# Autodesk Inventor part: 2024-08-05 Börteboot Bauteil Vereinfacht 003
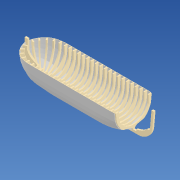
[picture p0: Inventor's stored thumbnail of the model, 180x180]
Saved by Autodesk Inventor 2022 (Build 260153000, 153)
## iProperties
Created: 2024-08
Part Number: 2024-08-05 Börteboot Bauteil Vereinfacht 003
Material: Generisch
Document SubType Name: Modellieren
Designer: i3meg
Density: 1 g/cm^3
Appearance: Vorgabe
Sheet Metal Rule: Standard_mm
Author: i3meg
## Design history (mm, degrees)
derived "2024-08-05 Börteboot 001.iam"
sketch "Skizze23"
  geometry: L1 (0, 40)-(16, 40) reference; L2 (16, 40)-(12, -2) reference; L3 (12, -2)-(7, -22) reference; L4 (7, -22)-(-2, -42) reference; L5 (-2, -42)-(-16, -60) reference; L6 (16, 40)-(18, 40); L7 (18, 40)-(14.861, -2.903); L8 (14.861, -2.903)-(13.907, -2.602); L9 (13.907, -2.602)-(9.669, -23.371); L10 (9.669, -23.371)-(8.806, -22.859); L11 (8.806, -22.859)-(0.442, -43.742); L12 (0.442, -43.742)-(-0.327, -43.096); L13 (-0.327, -43.096)-(-14.483, -62.588); L14 (-14.483, -62.588)-(-44.837, -65.349); L15 (-44.837, -65.349)-(-64.506, -66.341); L16 (-64.506, -66.341)-(-71.5, -79.942); L17 (-73.5, -76.942)-(-73.5, -79.942); L18 (-73.5, -79.942)-(-71.5, -79.942)
  constraints: 20 end point, 1 horizontal, 1 perpendicular, 1 vertical, 4 other
  dimensions: "d1821" = 2 distance of L1.end L6.end; "d1822" = 2 distance of L2.end L8.end; "d1823" = 3 distance of L2.end L7.end; "d1824" = 2 distance of L3.end L10.end; "d1825" = 3 distance of L3.end L9.end; "d1826" = 2 distance of L4.end L12.end; "d1827" = 3 distance of L4.end L11.end; "d1828" = 3 distance of L5.end L13.end; "d1829" = 3 distance of L17.start L17.end
sketch "Skizze24"
  geometry: L1 (16, 40)-(12, -4) reference; L2 (12, -4)-(8, -24) reference; L3 (8, -24)-(-1, -44) reference; L4 (-1, -44)-(-16, -62) reference; L5 (0, 40)-(16, 40) reference; L6 (16, 40)-(18, 40); L7 (18, 40)-(14.988, -4.272); L8 (14.988, -4.272)-(13.992, -4.181); L9 (13.992, -4.181)-(10.859, -24.909); L10 (10.859, -24.909)-(9.869, -24.713); L11 (9.869, -24.713)-(1.656, -45.395); L12 (1.656, -45.395)-(0.771, -44.93); L13 (0.771, -44.93)-(-14.749, -64.727); L14 (-73.5, -77.786)-(-73.5, -80.786); L15 (-73.5, -80.786)-(-71.5, -80.786); A1 r 219.794 centre (12.899, -279.885) between (-16, -62) and (-73.5, -77.786) reference; A2 r 202.647 centre (11.464, -265.671) between (-14.749, -64.727) and (-71.5, -80.786); 1 further point
  constraints: 20 end point, 2 point on circle, 1 centre point, 1 horizontal, 1 perpendicular, 1 vertical
  dimensions: "d161" = 2 distance of L1.start L6.end; "d166" = 2 distance of L1.end L8.end; "d167" = 3 distance of L1.end L7.end; "d169" = 2 distance of L2.end L10.end; "d170" = 3 distance of L2.end L9.end; "d173" = 2 distance of L3.end L12.end; "d174" = 3 distance of L3.end L11.end; "d175" = 3 distance of L4.end L13.end; "d1854" = 3 distance of L14.start L14.end
sketch "Skizze25"
  geometry: L1 (0, -46)-(-16, -64) reference; L2 (8, -26)-(0, -46) reference; L3 (12, -5)-(8, -26) reference; L4 (16, 40)-(12, -5) reference; L5 (16, 40)-(18, 40); L6 (18, 40)-(14.983, -5.319); L7 (14.983, -5.319)-(13.992, -5.177); L8 (13.992, -5.177)-(10.918, -26.695); L9 (10.918, -26.695)-(9.945, -26.465); L10 (9.945, -26.465)-(2.736, -47.231); L11 (2.736, -47.231)-(1.824, -46.821); L12 (1.824, -46.821)-(-14.767, -66.735); L13 (-73.5, -77.912)-(-73.5, -80.912); L14 (-73.5, -80.912)-(-71.5, -80.912); L15 (0, 40)-(16, 40) reference; A1 r 433.619 centre (-146.503, 349.514) between (-73.5, -77.915) and (-16, -64) reference; A2 r 310.184 centre (-118, 225.767) between (-71.5, -80.912) and (-14.767, -66.735); 1 further point
  constraints: 20 end point, 2 horizontal, 2 point on circle, 1 centre point, 1 perpendicular, 1 vertical
  dimensions: "d189" = 2 distance of L4.start L5.end; "d190" = 3 distance of L13.start L13.end; "d191" = 2 distance of L3.start L7.end; "d192" = 3 distance of L3.start L6.end; "d193" = 2 distance of L2.start L9.end; "d194" = 3 distance of L2.start L8.end; "d195" = 2 distance of L1.start L11.end; "d196" = 3 distance of L1.start L10.end; "d197" = 3 distance of L1.end L12.end; "d500" = 2 distance of L13.end L14.end
sketch "Skizze27"
  geometry: L1 (16, 40)-(12, -6) reference; L2 (12, -6)-(8, -27) reference; L3 (8, -27)-(0, -48) reference; L4 (0, -48)-(-16, -66) reference; L5 (16, 40)-(18, 40); L6 (18, 40)-(14.983, -6.315); L7 (14.983, -6.315)-(13.992, -6.173); L8 (13.992, -6.173)-(10.917, -27.702); L9 (10.917, -27.702)-(9.93, -27.524); L10 (9.93, -27.524)-(2.773, -49.144); L11 (2.773, -49.144)-(1.854, -48.75); L12 (1.854, -48.75)-(-13.819, -68.06); L13 (-73.5, -77.95)-(-73.5, -80.95); L14 (0, 40)-(16, 40) reference; A1 r 279.676 centre (-101.345, 200.336) between (-73.5, -77.95) and (-16, -66) reference; A2 r 259.061 centre (-97.972, 176.952) between (-73.5, -80.95) and (-13.819, -68.06); 1 further point
  constraints: 18 end point, 2 point on circle, 1 centre point, 1 horizontal, 1 perpendicular, 1 vertical
  dimensions: "d198" = 2 distance of L1.start L5.end; "d200" = 2 distance of L1.end L7.end; "d201" = 3 distance of L1.end L6.end; "d202" = 2 distance of L2.end L9.end; "d203" = 3 distance of L2.end L8.end; "d204" = 2 distance of L3.end L11.end; "d205" = 3 distance of L3.end L10.end; "d206" = 3 distance of L4.end L12.end; "d207" = 3 distance of L13.start L13.end
sketch "Skizze28"
  geometry: L1 (12, -6)-(16, 40) reference; L2 (8, -28)-(12, -6) reference; L3 (0, -49)-(8, -28) reference; L4 (-16, -67)-(0, -49) reference; L5 (-73.5, -77.992)-(-73.5, -80.992); L6 (16, 40)-(18, 40); L7 (18, 40)-(14.947, -6.561); L8 (14.947, -6.561)-(13.965, -6.374); L9 (13.965, -6.374)-(10.76, -29.176); L10 (10.76, -29.176)-(9.795, -28.883); L11 (9.795, -28.883)-(2.778, -50.133); L12 (2.778, -50.133)-(1.822, -49.824); L13 (1.822, -49.824)-(-13.372, -68.446); L14 (16, 40)-(0, 40) reference; A1 r 171.355 centre (-76.452, 93.337) between (-73.5, -77.992) and (-16, -67) reference; A2 r 176.524 centre (-78.941, 95.448) between (-73.5, -80.992) and (-13.372, -68.446); 1 further point
  constraints: 18 end point, 2 point on circle, 1 centre point, 1 horizontal, 1 vertical
  dimensions: "d224" = 3 distance of L5.start L5.end; "d225" = 2 distance of L1.end L6.end; "d226" = 2 distance of L1.start L8.end; "d227" = 3 distance of L1.start L7.end; "d228" = 2 distance of L2.start L10.end; "d229" = 3 distance of L2.start L9.end; "d230" = 2 distance of L3.start L12.end; "d231" = 3 distance of L3.start L11.end; "d232" = 3 distance of L4.start L13.end
sketch "Skizze37"
  geometry: L1 (12, -6)-(16, 40) reference; L2 (8, -28)-(12, -6) reference; L3 (0, -49)-(8, -28) reference; L4 (-16, -67)-(0, -49) reference; L5 (-73.5, -77.992)-(-73.5, -80.992); L6 (16, 40)-(0, 40) reference; L7 (16, 40)-(18, 40); L8 (18, 40)-(14.985, -6.302); L9 (14.985, -6.302)-(13.993, -6.17); L10 (13.993, -6.17)-(10.905, -28.749); L11 (10.905, -28.749)-(9.955, -28.421); L12 (9.955, -28.421)-(2.818, -50.028); L13 (2.818, -50.028)-(1.868, -49.714); L14 (1.868, -49.714)-(-13.461, -68.598); A1 r 171.355 centre (-76.452, 93.337) between (-73.5, -77.992) and (-16, -67) reference; A2 r 170.875 centre (-77.466, 89.837) between (-73.5, -80.992) and (-13.461, -68.598); 1 further point
  constraints: 18 end point, 2 point on circle, 1 centre point, 1 horizontal, 1 perpendicular, 1 vertical
  dimensions: "d286" = 3 distance of L5.start L5.end; "d287" = 2 distance of L1.end L7.end; "d288" = 2 distance of L1.start L9.end; "d289" = 3 distance of L1.start L8.end; "d290" = 2 distance of L2.start L11.end; "d291" = 3 distance of L2.start L10.end; "d292" = 2 distance of L3.start L13.end; "d293" = 3 distance of L3.start L12.end; "d294" = 3 distance of L4.start L14.end
sketch "Skizze38"
  geometry: L1 (9.955, -28.421)-(2.818, -50.028); L2 (2.818, -50.028)-(1.868, -49.714); L3 (1.868, -49.714)-(-13.461, -68.598); L4 (-73.5, -77.992)-(-73.5, -80.992); L5 (10.905, -28.749)-(9.955, -28.421); L6 (13.993, -6.17)-(10.905, -28.749); L7 (14.985, -6.302)-(13.993, -6.17); L8 (16, 40)-(18, 40); L9 (18, 40)-(14.985, -6.302); L10 (-16, -67)-(0, -49) reference; L11 (0, -49)-(8, -28) reference; L12 (8, -28)-(12, -6) reference; L13 (12, -6)-(16, 40) reference; L14 (16, 40)-(0, 40) reference; A1 r 170.875 centre (-77.466, 89.837) between (-73.5, -80.992) and (-13.461, -68.598); A2 r 171.355 centre (-76.452, 93.337) between (-73.5, -77.992) and (-16, -67) reference; 1 further point
  constraints: 18 end point, 2 point on circle, 1 centre point, 1 horizontal, 1 perpendicular, 1 vertical
  dimensions: "d295" = 3 distance of L4.start L4.end; "d296" = 2 distance of L8.start L8.end; "d533" = 2 distance of L12.end L6.start; "d534" = 3 distance of L12.end L7.start; "d535" = 2 distance of L11.end L1.start; "d536" = 3 distance of L11.end L5.start; "d537" = 2 distance of L10.end L2.end; "d538" = 3 distance of L10.end L1.end; "d539" = 3 distance of L10.start L3.end
sketch "Skizze39"
  geometry: L1 (9.955, -28.421)-(2.818, -50.028); L2 (2.818, -50.028)-(1.868, -49.714); L3 (1.868, -49.714)-(-13.461, -68.598); L4 (-73.5, -77.992)-(-73.5, -80.992); L5 (10.905, -28.749)-(9.955, -28.421); L6 (13.993, -6.17)-(10.905, -28.749); L7 (14.985, -6.302)-(13.993, -6.17); L8 (16, 40)-(18, 40); L9 (18, 40)-(14.985, -6.302); L10 (16, 40)-(0, 40) reference; L11 (12, -6)-(16, 40) reference; L12 (8, -28)-(12, -6) reference; L13 (0, -49)-(8, -28) reference; L14 (-16, -67)-(0, -49) reference; A1 r 170.875 centre (-77.466, 89.837) between (-73.5, -80.992) and (-13.461, -68.598); A2 r 171.355 centre (-76.452, 93.337) between (-73.5, -77.992) and (-16, -67) reference; 1 further point
  constraints: 18 end point, 2 point on circle, 1 centre point, 1 horizontal, 1 perpendicular, 1 vertical
  dimensions: "d304" = 3 distance of L4.start L4.end; "d305" = 2 distance of L8.start L8.end; "d540" = 2 distance of L11.start L6.start; "d541" = 3 distance of L11.start L7.start; "d542" = 2 distance of L12.start L1.start; "d543" = 3 distance of L12.start L5.start; "d544" = 2 distance of L13.start L2.end; "d545" = 3 distance of L13.start L1.end; "d546" = 3 distance of L14.start L3.end
sketch "Skizze40"
  geometry: L1 (9.955, -28.421)-(2.818, -50.028); L2 (2.818, -50.028)-(1.868, -49.714); L3 (1.868, -49.714)-(-13.461, -68.598); L4 (-73.5, -77.992)-(-73.5, -80.992); L5 (10.905, -28.749)-(9.955, -28.421); L6 (13.993, -6.17)-(10.905, -28.749); L7 (14.985, -6.302)-(13.993, -6.17); L8 (16, 40)-(18, 40); L9 (18, 40)-(14.985, -6.302); L10 (-16, -67)-(0, -49) reference; L11 (0, -49)-(8, -28) reference; L12 (8, -28)-(12, -6) reference; L13 (12, -6)-(16, 40) reference; L14 (16, 40)-(0, 40) reference; A1 r 170.875 centre (-77.466, 89.837) between (-73.5, -80.992) and (-13.461, -68.598); A2 r 171.355 centre (-76.452, 93.337) between (-73.5, -77.992) and (-16, -67) reference; 1 further point
  constraints: 18 end point, 2 point on circle, 1 centre point, 1 horizontal, 1 perpendicular, 1 vertical
  dimensions: "d313" = 3 distance of L4.start L4.end; "d314" = 2 distance of L8.start L8.end; "d547" = 2 distance of L12.end L6.start; "d548" = 3 distance of L12.end L7.start; "d549" = 2 distance of L11.end L1.start; "d550" = 3 distance of L11.end L5.start; "d551" = 2 distance of L10.end L2.end; "d552" = 3 distance of L10.end L1.end; "d553" = 3 distance of L10.start L3.end
sketch "Skizze41"
  geometry: L1 (9.955, -28.421)-(2.818, -50.028); L2 (2.818, -50.028)-(1.868, -49.714); L3 (1.868, -49.714)-(-13.461, -68.598); L4 (-73.5, -77.992)-(-73.5, -80.992); L5 (10.905, -28.749)-(9.955, -28.421); L6 (13.993, -6.17)-(10.905, -28.749); L7 (14.985, -6.302)-(13.993, -6.17); L8 (16, 40)-(18, 40); L9 (18, 40)-(14.985, -6.302); L10 (-16, -67)-(0, -49) reference; L11 (0, -49)-(8, -28) reference; L12 (8, -28)-(12, -6) reference; L13 (12, -6)-(16, 40) reference; L14 (16, 40)-(0, 40) reference; A1 r 170.875 centre (-77.466, 89.837) between (-73.5, -80.992) and (-13.461, -68.598); A2 r 171.355 centre (-76.452, 93.337) between (-73.5, -77.992) and (-16, -67) reference; 1 further point
  constraints: 18 end point, 2 point on circle, 1 centre point, 1 horizontal, 1 perpendicular, 1 vertical
  dimensions: "d322" = 3 distance of L4.start L4.end; "d323" = 2 distance of L8.start L8.end; "d554" = 2 distance of L12.end L6.start; "d555" = 3 distance of L12.end L7.start; "d556" = 2 distance of L11.end L1.start; "d557" = 3 distance of L11.end L5.start; "d558" = 2 distance of L10.end L2.end; "d559" = 3 distance of L10.end L1.end; "d560" = 3 distance of L10.start L3.end
sketch "Skizze42"
  geometry: L1 (9.955, -28.421)-(2.818, -50.028); L2 (2.818, -50.028)-(1.868, -49.714); L3 (1.868, -49.714)-(-13.461, -68.598); L4 (-73.5, -77.992)-(-73.5, -80.992); L5 (10.905, -28.749)-(9.955, -28.421); L6 (13.993, -6.17)-(10.905, -28.749); L7 (14.985, -6.302)-(13.993, -6.17); L8 (16, 40)-(18, 40); L9 (18, 40)-(14.985, -6.302); L10 (16, 40)-(0, 40) reference; L11 (12, -6)-(16, 40) reference; L12 (8, -28)-(12, -6) reference; L13 (0, -49)-(8, -28) reference; L14 (-16, -67)-(0, -49) reference; A1 r 170.875 centre (-77.466, 89.837) between (-73.5, -80.992) and (-13.461, -68.598); A2 r 171.355 centre (-76.452, 93.337) between (-73.5, -77.992) and (-16, -67) reference; 1 further point
  constraints: 18 end point, 2 point on circle, 1 centre point, 1 horizontal, 1 perpendicular, 1 vertical
  dimensions: "d331" = 3 distance of L4.start L4.end; "d332" = 2 distance of L8.start L8.end; "d561" = 2 distance of L11.start L6.start; "d562" = 3 distance of L11.start L7.start; "d563" = 2 distance of L12.start L1.start; "d564" = 3 distance of L12.start L5.start; "d566" = 2 distance of L13.start L2.end; "d567" = 3 distance of L13.start L1.end; "d568" = 3 distance of L14.start L3.end
sketch "Skizze43"
  geometry: L1 (9.955, -28.421)-(2.818, -50.028); L2 (2.818, -50.028)-(1.868, -49.714); L3 (1.868, -49.714)-(-13.461, -68.598); L4 (-73.5, -77.992)-(-73.5, -80.992); L5 (10.905, -28.749)-(9.955, -28.421); L6 (13.993, -6.17)-(10.905, -28.749); L7 (14.985, -6.302)-(13.993, -6.17); L8 (16, 40)-(18, 40); L9 (18, 40)-(14.985, -6.302); L10 (-16, -67)-(0, -49) reference; L11 (0, -49)-(8, -28) reference; L12 (8, -28)-(12, -6) reference; L13 (12, -6)-(16, 40) reference; L14 (16, 40)-(0, 40) reference; A1 r 170.875 centre (-77.466, 89.837) between (-73.5, -80.992) and (-13.461, -68.598); A2 r 171.355 centre (-76.452, 93.337) between (-73.5, -77.992) and (-16, -67) reference; 1 further point
  constraints: 18 end point, 2 point on circle, 1 centre point, 1 horizontal, 1 perpendicular, 1 vertical
  dimensions: "d340" = 3 distance of L4.start L4.end; "d341" = 2 distance of L8.start L8.end; "d569" = 2 distance of L12.end L6.start; "d570" = 3 distance of L12.end L7.start; "d571" = 2 distance of L11.end L1.start; "d572" = 3 distance of L11.end L5.start; "d573" = 2 distance of L10.end L2.end; "d574" = 3 distance of L10.end L1.end; "d575" = 3 distance of L10.start L3.end
sketch "Skizze44"
  geometry: L1 (9.955, -28.421)-(2.818, -50.028); L2 (2.818, -50.028)-(1.868, -49.714); L3 (1.868, -49.714)-(-13.461, -68.598); L4 (-73.5, -77.992)-(-73.5, -80.992); L5 (10.905, -28.749)-(9.955, -28.421); L6 (13.993, -6.17)-(10.905, -28.749); L7 (14.985, -6.302)-(13.993, -6.17); L8 (16, 40)-(18, 40); L9 (18, 40)-(14.985, -6.302); L10 (-16, -67)-(0, -49) reference; L11 (0, -49)-(8, -28) reference; L12 (8, -28)-(12, -6) reference; L13 (12, -6)-(16, 40) reference; L14 (16, 40)-(0, 40) reference; A1 r 170.875 centre (-77.466, 89.837) between (-73.5, -80.992) and (-13.461, -68.598); A2 r 171.355 centre (-76.452, 93.337) between (-73.5, -77.992) and (-16, -67) reference; 1 further point
  constraints: 18 end point, 2 point on circle, 1 centre point, 1 horizontal, 1 perpendicular, 1 vertical
  dimensions: "d349" = 3 distance of L4.start L4.end; "d350" = 2 distance of L8.start L8.end; "d576" = 2 distance of L12.end L6.start; "d577" = 3 distance of L12.end L7.start; "d578" = 2 distance of L11.end L1.start; "d579" = 3 distance of L11.end L5.start; "d580" = 2 distance of L10.end L2.end; "d581" = 3 distance of L10.end L1.end; "d582" = 3 distance of L10.start L3.end
sketch "Skizze45"
  geometry: L1 (9.955, -28.421)-(2.818, -50.028); L2 (2.818, -50.028)-(1.868, -49.714); L3 (1.868, -49.714)-(-13.461, -68.598); L4 (-73.5, -77.992)-(-73.5, -80.992); L5 (10.905, -28.749)-(9.955, -28.421); L6 (13.993, -6.17)-(10.905, -28.749); L7 (14.985, -6.302)-(13.993, -6.17); L8 (16, 40)-(18, 40); L9 (18, 40)-(14.985, -6.302); L10 (-16, -67)-(0, -49) reference; L11 (0, -49)-(8, -28) reference; L12 (8, -28)-(12, -6) reference; L13 (12, -6)-(16, 40) reference; L14 (16, 40)-(0, 40) reference; A1 r 170.875 centre (-77.466, 89.837) between (-73.5, -80.992) and (-13.461, -68.598); A2 r 171.355 centre (-76.452, 93.337) between (-73.5, -77.992) and (-16, -67) reference; 1 further point
  constraints: 18 end point, 2 point on circle, 1 centre point, 1 horizontal, 1 perpendicular, 1 vertical
  dimensions: "d358" = 3 distance of L4.start L4.end; "d359" = 2 distance of L8.start L8.end; "d583" = 2 distance of L12.end L6.start; "d584" = 3 distance of L12.end L7.start; "d585" = 2 distance of L11.end L1.start; "d586" = 3 distance of L11.end L5.start; "d587" = 2 distance of L10.end L2.end; "d588" = 3 distance of L10.end L1.end; "d589" = 3 distance of L10.start L3.end
sketch "Skizze46"
  geometry: L1 (9.955, -28.421)-(2.818, -50.028); L2 (2.818, -50.028)-(1.868, -49.714); L3 (1.868, -49.714)-(-13.461, -68.598); L4 (-73.5, -77.992)-(-73.5, -80.992); L5 (10.905, -28.749)-(9.955, -28.421); L6 (13.993, -6.17)-(10.905, -28.749); L7 (14.985, -6.302)-(13.993, -6.17); L8 (16, 40)-(18, 40); L9 (18, 40)-(14.985, -6.302); L10 (-16, -67)-(0, -49) reference; L11 (0, -49)-(8, -28) reference; L12 (8, -28)-(12, -6) reference; L13 (12, -6)-(16, 40) reference; L14 (16, 40)-(0, 40) reference; A1 r 170.875 centre (-77.466, 89.837) between (-73.5, -80.992) and (-13.461, -68.598); A2 r 171.355 centre (-76.452, 93.337) between (-73.5, -77.992) and (-16, -67) reference; 1 further point
  constraints: 18 end point, 2 point on circle, 1 centre point, 1 horizontal, 1 perpendicular, 1 vertical
  dimensions: "d367" = 3 distance of L4.start L4.end; "d368" = 2 distance of L8.start L8.end; "d590" = 2 distance of L12.end L6.start; "d591" = 3 distance of L12.end L7.start; "d592" = 2 distance of L11.end L1.start; "d593" = 3 distance of L11.end L5.start; "d594" = 2 distance of L10.end L2.end; "d595" = 3 distance of L10.end L1.end; "d596" = 3 distance of L10.start L3.end
sketch "Skizze47"
  geometry: L1 (9.407, -27.602)-(2.829, -48.999); L2 (2.829, -48.999)-(1.872, -48.705); L3 (1.872, -48.705)-(-13.883, -68.599); L4 (-73.5, -77.958)-(-73.5, -80.958); L5 (10.391, -27.803)-(9.407, -27.602); L6 (13.992, -6.173)-(10.391, -27.803); L7 (14.989, -6.26)-(13.992, -6.173); L8 (18, 40)-(14.989, -6.26); L9 (16, 40)-(0, 40); L10 (18, 40)-(16, 40); L11 (-16.421, -67)-(0, -48) reference; L12 (0, -48)-(7.5, -27) reference; L13 (7.5, -27)-(12, -6) reference; L14 (12, -6)-(16, 40) reference; A1 r 170.875 centre (-77.82, 89.863) between (-73.5, -80.958) and (-13.883, -68.599); A2 r 279.676 centre (-97.402, 200.695) between (-73.5, -77.958) and (-16.421, -67) reference; 1 further point
  constraints: 18 end point, 2 point on circle, 1 centre point, 1 horizontal, 1 perpendicular, 1 vertical
  dimensions: "d376" = 3 distance of L4.start L4.end; "d377" = 2 distance of L14.end L8.start; "d947" = 2 distance of L13.end L6.start; "d948" = 3 distance of L13.end L7.start; "d949" = 2 distance of L12.end L1.start; "d950" = 3 distance of L12.end L5.start; "d951" = 2 distance of L11.end L2.end; "d952" = 3 distance of L11.end L1.end; "d953" = 3 distance of L11.start L3.end
sketch "Skizze48"
  geometry: L1 (12, -5)-(16, 40) reference; L2 (7, -26)-(12, -5) reference; L3 (-1, -46)-(7, -26) reference; L4 (-17, -65)-(-1, -46) reference; L5 (-73.5, -77.921)-(-73.5, -80.921); L6 (0, 40)-(16, 40) reference; L7 (16, 40)-(18, 40); L8 (18, 40)-(14.976, -5.383); L9 (14.976, -5.383)-(13.983, -5.258); L10 (13.983, -5.258)-(9.918, -26.697); L11 (9.918, -26.697)-(8.961, -26.393); L12 (8.961, -26.393)-(1.755, -47.189); L13 (1.755, -47.189)-(0.806, -46.86); L14 (0.806, -46.86)-(-15.718, -67.712); L15 (-73.5, -80.921)-(-71.5, -80.921); A1 r 433.619 centre (-141.7, 350.301) between (-73.5, -77.921) and (-17, -65) reference; A2 r 288.501 centre (-109.755, 205.033) between (-71.5, -80.921) and (-15.718, -67.712); 1 further point
  constraints: 20 end point, 2 horizontal, 2 point on circle, 1 centre point, 1 perpendicular, 1 vertical
  dimensions: "d425" = 3 distance of L5.start L5.end; "d426" = 2 distance of L1.end L7.end; "d427" = 2 distance of L1.start L9.end; "d428" = 3 distance of L1.start L8.end; "d429" = 2 distance of L2.start L11.end; "d430" = 3 distance of L2.start L10.end; "d431" = 2 distance of L3.start L13.end; "d432" = 3 distance of L3.start L12.end; "d433" = 3 distance of L4.start L14.end; "d501" = 2 distance of L5.end L15.end
sketch "Skizze49"
  geometry: L1 (12, -4)-(16, 40) reference; L2 (6.5, -24)-(12, -4) reference; L3 (-3, -44)-(6.5, -24) reference; L4 (-18, -62)-(-3, -44) reference; L5 (-73.5, -77.772)-(-73.5, -80.772); L6 (16, 40)-(18, 40); L7 (18, 40)-(14.988, -4.272); L8 (14.988, -4.272)-(13.992, -4.181); L9 (13.992, -4.181)-(9.365, -24.889); L10 (9.365, -24.889)-(8.428, -24.532); L11 (8.428, -24.532)-(-0.257, -45.215); L12 (-0.257, -45.215)-(-1.132, -44.714); L13 (-1.132, -44.714)-(-16.717, -64.712); L14 (-73.5, -80.772)-(-71.5, -80.772); L15 (16, 40)-(0, 40) reference; A1 r 219.794 centre (14.094, -279.438) between (-18, -62) and (-73.5, -77.853) reference; A2 r 235.378 centre (21.621, -296.947) between (-16.717, -64.712) and (-71.5, -80.772); 1 further point
  constraints: 20 end point, 2 horizontal, 2 point on circle, 1 centre point, 1 vertical
  dimensions: "d434" = 3 distance of L5.start L5.end; "d435" = 2 distance of L1.end L6.end; "d436" = 2 distance of L1.start L8.end; "d437" = 3 distance of L1.start L7.end; "d438" = 2 distance of L2.start L10.end; "d439" = 3 distance of L2.start L9.end; "d440" = 3 distance of L13.end L4.start; "d450" = 2 distance of L3.start L12.end; "d451" = 3 distance of L3.start L11.end; "d502" = 2 distance of L5.end L14.end
sketch "Skizze51"
  geometry: L1 (12, -3)-(16, 40) reference; L2 (5, -22)-(12, -3) reference; L3 (-5, -41)-(5, -22) reference; L4 (-20, -57)-(-5, -41) reference; L5 (-73.5, -76.936)-(-73.5, -79.936); L6 (16, 40)-(18, 40); L7 (18, 40)-(14.987, -3.278); L8 (14.987, -3.278)-(13.991, -3.185); L9 (13.991, -3.185)-(7.751, -23.196); L10 (7.751, -23.196)-(6.845, -22.771); L11 (6.845, -22.771)-(-2.328, -42.363); L12 (-2.328, -42.363)-(-3.246, -41.961); L13 (-3.246, -41.961)-(-18.862, -59.776); L14 (-73.5, -79.936)-(-71.5, -79.936); L15 (16, 40)-(0, 40) reference; A1 r 155.061 centre (9.356, -212.248) between (-18.862, -59.776) and (-71.5, -79.936); 1 further point
  constraints: 20 end point, 2 horizontal, 2 point on circle, 1 centre point, 1 perpendicular, 1 vertical, 1 other
  dimensions: "d452" = 3 distance of L5.start L5.end; "d453" = 2 distance of L1.end L6.end; "d454" = 3 distance of L4.start L13.end; "d455" = 2 distance of L1.start L8.end; "d456" = 3 distance of L1.start L7.end; "d457" = 2 distance of L2.start L10.end; "d458" = 3 distance of L2.start L9.end; "d459" = 2 distance of L3.start L12.end; "d460" = 3 distance of L3.start L11.end; "d503" = 2 distance of L5.end L14.end
sketch "Skizze64"
  geometry: L1 (16, 40)-(0, 40) reference; L2 (12, -1)-(16, 40) reference; L3 (4, -20)-(12, -1) reference; L4 (-7, -38)-(4, -20) reference; L5 (-23, -53)-(-7, -38) reference; L6 (-72.5, -75.584)-(-72.5, -78.584); L7 (-72.5, -78.584)-(-70.5, -78.584); L8 (16, 40)-(18, 40); L9 (18, 40)-(14.986, -1.291); L10 (14.986, -1.291)-(13.991, -1.194); L11 (13.991, -1.194)-(6.839, -20.969); L12 (6.839, -20.969)-(5.92, -20.56); L13 (5.92, -20.56)-(-4.44, -39.564); L14 (-4.44, -39.564)-(-5.293, -39.043); L15 (-5.293, -39.043)-(-21.189, -55.392); A1 r 119.222 centre (3.554, -172.018) between (-21.189, -55.392) and (-70.5, -78.584); 2 further points
  constraints: 20 end point, 2 point on circle, 1 centre point, 1 horizontal, 1 perpendicular, 1 vertical, 1 other
  dimensions: "d1154" = 3 distance of L6.start L6.end; "d1155" = 2 distance of L6.end L7.end; "d1156" = 2 distance of L1.start L8.end; "d1157" = 2 distance of L2.start L10.end; "d1158" = 3 distance of L2.start L9.end; "d1159" = 2 distance of L3.start L12.end; "d1160" = 3 distance of L3.start L11.end; "d1162" = 2 distance of L4.start L14.end; "d1163" = 3 distance of L4.start L13.end; "d1164" = 3 distance of L5.start L15.end
workplane "Arbeitsebene10"
sketch "Skizze66"
  geometry: L1 (-149, 78)-(-149, 73.5) reference; L2 (-133, 73.5)-(-149, 73.5) reference; L3 (-133, 78)-(-133, 73.5) reference; L4 (-149, 78)-(545.913, 78); L5 (509.887, 78)-(509.887, 73.5) reference; L6 (521.933, 73.5)-(509.887, 73.5) reference; L7 (521.933, 78)-(521.933, 73.5) reference; L8 (-149, 82.5)-(-149, 73.5) reference; L9 (419.933, 78)-(532.121, 78); L10 (419.933, 78)-(528.824, 78); L11 (419.933, 78)-(532.968, 78); L12 (419.933, 78)-(537.839, 78); L13 (-47, 78)-(63.58, 78); L14 (-47, 78)-(63.869, 78); L15 (-47, 78)-(64.441, 78); L16 (-47, 78)-(66.003, 78); L17 (521.933, 78)-(509.887, 78) reference; L18 (-133, 78)-(-149, 78) reference; L19 (-104, 73.5)-(441, 73.5) reference; L20 (-29, 63)-(-29, 0) reference; L21 (419.933, 73.5)-(444.387, -41.549); L22 (414, 1)-(414, -15) reference; L23 (-49.182, 75.75)-(66.519, 75.75); L24 (-35, 75.75)-(-53.663, -30.096); L25 (-29, 78)-(-29, 63) reference; L26 (-29, 0)-(-29, -16) reference; L27 (-45, 75.75)-(-82.627, -17.38); L28 (-55, 75.75)-(-113.479, -7.767); L29 (-68, 75.75)-(-134.552, 17.897); L30 (-87, 75.75)-(-153.724, 43.207); L31 (429.933, 75.75)-(466.475, -14.695); L32 (439.933, 75.75)-(488.874, 3.191); L33 (449.933, 75.75)-(506.944, 22.586); L34 (459.933, 75.75)-(517.489, 45.147); C1 r 92.5 at (-47, 78); C2 r 92.5 at (419.933, 78); A1 r 1.607 centre (418.36, 73.166) between (419.933, 73.5) and (419.933, 73.5); 1 further point
  constraints: 40 end point, 10 horizontal, 5 point on line, 3 centre point, 2 point on circle, 1 midpoint, 1 tangent
  dimensions: "d1205" = 185 diameter of C1; "d1206" = 102 distance from line of L8 L13.start; "d1207" = 185 diameter of C2; "d1208" = 102 distance from line of L7 L9.start; "d1459" = 12 deg angle of L22 L21; "d1521" = 6 distance from line of L25 L24.start; "d1522" = 10 deg angle of L26 L24; "d1523" = 10 distance of L24.start L27.start; "d1524" = 12 deg angle of L24 L27; "d1525" = 10 distance of L27.start L28.start; "d1526" = 13 deg angle of L27 L28; "d1527" = 13 distance of L28.start L29.start; "d1528" = 14 deg angle of L28 L29; "d1529" = 19 distance of L29.start L30.start; "d1530" = 15 deg angle of L29 L30; "d1531" = 10 horizontal distance of L21.start L31.start; "d1532" = 10 deg angle of L21 L31; "d1533" = 10 distance of L31.start L32.start; "d1534" = 12 deg angle of L32 L31; "d1535" = 10 distance of L32.start L33.start; "d1536" = 10 distance of L33.start L34.start; "d1537" = 13 deg angle of L33 L32; "d1538" = 15 deg angle of L33 L34
  node "Projizierte Kontur63"
  node "Projizierte Kontur64"
workplane "Arbeitsebene15"
sketch "Skizze80"
  geometry: L1 (95.58, -2.549)-(95.58, 13.005); L2 (0, 91.743)-(40, 86.743); L3 (35, 75.743)-(0, 75.743); L4 (40, 86.743)-(59, 80.743); L5 (59, 80.743)-(78, 72.743); L6 (78, 72.743)-(96, 59.743); L7 (95.58, -2.549)-(114.959, -2.549); L8 (114.5, 2.665)-(114.959, -2.549); L9 (0, 75.743)-(0, 91.743); L10 (-69.42, 202.197)-(-69.42, -260.249) reference; L11 (165.084, -24.257)-(-108.504, -24.257) reference; 2 further points; 1 other entity
  constraints: 18 end point, 1 vertical, 7 other
  dimensions: "d1542" = 100 distance between parallel lines of L3 L11; "d1543" = 16 distance of L3.end L2.start; "d1544" = 165 distance between parallel lines of L10 L1; "d1545" = 35 distance from line of L9 L3.start; "d1546" = 69.42029 distance between parallel lines of L10 L9; "d1547" = 40 distance from line of L2.end L9; "d1807" = 19 horizontal distance of L4.end L2.end; "d1808" = 19 horizontal distance of L5.end L4.end; "d1809" = 18 horizontal distance of L6.end L5.end; "d1846" = 97 distance from line of L11 L5.end; "d1847" = 84 distance from line of L11 L6.end; "d1852" = 105 distance from line of L11 L4.end; "d1853" = 111 distance from line of L11 L2.end
extrude "Extrusion19" join sketch "Skizze80" distance "d1540" = 6; taper "d1541" = 0 deg
workplane "Arbeitsebene16"
sketch "Skizze81"
  geometry: L1 (0, 75.114)-(33, 75.114); L2 (0, 91.114)-(0, 75.114); L3 (35, 85.614)-(0, 91.114); L4 (53, 79.614)-(35, 85.614); L5 (93.58, 14.427)-(93.58, -3.051); L6 (93.58, -3.051)-(111.213, -3.051); L7 (71, 70.614)-(53, 79.614); L8 (89, 59.614)-(71, 70.614); L9 (111.213, 4.975)-(111.213, -3.051); L10 (-69.42, 241.226)-(-69.42, -400.95) reference; L11 (165.084, -50.386)-(-108.504, -50.386) reference; 2 further points; 1 other entity
  constraints: 18 end point, 1 vertical, 7 other
  dimensions: "d1553" = 69.42029 distance between parallel lines of L10 L2; "d1554" = 125.5 distance between parallel lines of L11 L1; "d1555" = 16 distance of L1.start L2.start; "d1556" = 33 distance of L1.start L1.end; "d1557" = 35 distance from line of L3.start L2; "d1803" = 130 distance from line of L11 L4.start; "d1804" = 121 distance from line of L11 L7.start; "d1805" = 110 distance from line of L11 L8.start; "d1806" = 136 distance from line of L11 L3.start; "d2263" = 18 horizontal distance of L4.start L3.start; "d2264" = 18 horizontal distance of L7.start L4.start; "d2265" = 18 horizontal distance of L8.start L7.start
extrude "Extrusion20" join sketch "Skizze81" distance "d1549" = 6; taper "d1550" = 0 deg
workplane "Arbeitsebene17"
sketch "Skizze83"
  geometry: L1 (92.58, -4.895)-(112.58, -4.895); L2 (79.58, 57.469)-(63, 67.969); L3 (63, 67.969)-(46, 75.969); L4 (46, 75.969)-(29, 80.969); L5 (29, 80.969)-(0, 85.969); L6 (0, 85.969)-(0, 69.969); L7 (0, 69.969)-(22.505, 69.969); L8 (92.58, 9.184)-(92.58, -4.895); L9 (92.58, -4.895)-(112.58, -4.895); L10 (112.58, 0.34)-(112.58, -4.895); L11 (-69.42, 267.71)-(-69.42, -537.283) reference; L12 (165.084, -80.031)-(-108.504, -80.031) reference; 2 further points; 1 other entity
  constraints: 20 end point, 1 horizontal, 1 vertical, 10 other
  dimensions: "d1559" = 69.42029 distance between parallel lines of L11 L6; "d1563" = 162 distance between parallel lines of L11 L8; "d1564" = 20 distance between parallel lines of L10 L8; "d1565" = 149 distance from line of L11 L2.start; "d1566" = 29 distance from line of L6 L4.end; "d1579" = 150 distance between parallel lines of L12 L7; "d1580" = 16 distance of L5.end L6.end; "d1799" = 137.5 distance from line of L12 L2.start; "d1800" = 17 horizontal distance of L4.end L3.end; "d1801" = 17 horizontal distance of L3.end L2.end; "d1802" = 148 distance from line of L12 L2.end; "d2245" = 156 distance from line of L12 L3.end; "d2246" = 161 distance from line of L12 L4.end
extrude "Extrusion22" join sketch "Skizze83" distance "d1567" = 6; taper "d1568" = 0 deg
workplane "Arbeitsebene18"
sketch "Skizze84"
  geometry: L1 (0, 57.926)-(25, 57.926); L2 (24, 71.131)-(0, 73.926); L3 (40, 67.888)-(24, 71.131); L4 (56, 59.888)-(40, 67.888); L5 (70, 49.888)-(56, 59.888); L6 (90.58, 3.87)-(90.58, -10.846); L7 (90.58, -10.846)-(110.58, -10.846); L8 (110.58, -10.846)-(110.58, -5.765); L9 (0, 73.926)-(0, 57.926); L10 (-69.42, 275.079)-(-69.42, -658.915) reference; L11 (165.084, -113.112)-(-108.504, -113.112) reference; L12 (0, 0)-(0, 88.182) reference; 2 further points; 1 other entity
  constraints: 18 end point, 7 other
  dimensions: "d1571" = 69.42029 distance between parallel lines of L10 L9; "d1572" = 171.03848 distance between parallel lines of L11 L1; "d1573" = 16 distance of L2.end L1.start; "d1574" = 25 distance of L1.start L1.end; "d1575" = 24 horizontal distance of L2.start L2.end; "d1576" = 160 distance between parallel lines of L10 L6; "d1794" = 14 horizontal distance of L5.start L4.start; "d1795" = 16 horizontal distance of L4.start L3.start; "d1796" = 16 horizontal distance of L3.start L2.start; "d1797" = 163 distance from line of L11 L5.start; "d1798" = 173 distance from line of L11 L4.start; "d2063" = 181 distance from line of L11 L3.start
extrude "Extrusion23" join sketch "Skizze84" distance "d1577" = 6; taper "d1578" = 0 deg
workplane "Arbeitsebene19"
sketch "Skizze85"
  geometry: L1 (0, 37.845)-(17.195, 37.845); L2 (80.58, -14.142)-(80.58, -26); L3 (80.58, -26)-(110.58, -26); L4 (66, 24.845)-(51, 37.845); L5 (51, 37.845)-(37, 46.845); L6 (37, 46.845)-(22, 52.845); L7 (22, 52.845)-(0, 53.845); L8 (0, 53.845)-(0, 37.845); L9 (-69.42, 297.978)-(-69.42, -761.789) reference; L10 (259.95, -150.155)-(-124.315, -150.155) reference; L11 (110.58, -26)-(110.58, -21.093) reference; L12 (110.58, -26)-(110.58, -20.227); A1 r 167.263 centre (205.055, 117.799) between (66, 24.845) and (110.58, -20.227); A2 r 93.737 centre (-4.574, -53.329) between (80.58, -14.145) and (17.195, 37.845); 2 further points
  constraints: 18 end point, 4 point on circle, 2 centre point, 1 collinear, 1 point on line
  dimensions: "d1582" = 69.42029 distance between parallel lines of L9 L8; "d1583" = 188 distance between parallel lines of L10 L1; "d1584" = 150 distance between parallel lines of L9 L2; "d1585" = 16 distance of L7.end L1.start; "d1588" = 15 horizontal distance of L5.end L6.end; "d1589" = 14 horizontal distance of L5.end L4.end; "d1590" = 15 horizontal distance of L4.end L4.start; "d1591" = 175 distance from line of L10 L4.start; "d1592" = 188 distance from line of L10 L4.end; "d2068" = 203 distance from line of L10 L6.end; "d2247" = 22 horizontal distance of L7.end L6.end; "d2248" = 197 distance from line of L10 L5.end
extrude "Extrusion24" join sketch "Skizze85" distance "d1586" = 6; taper "d1587" = 0 deg
extrude "Extrusion25" cut sketch "Skizze86" extent not by distance; stored distance "d1593" = 0; taper "d1594" = 0 deg
sketch "Skizze88"
  geometry: L1 (91.743, 0)-(75.743, 0) reference; L2 (86.743, -40)-(91.743, 0) reference; L3 (80.743, -59)-(86.743, -40) reference; L4 (72.743, -78)-(80.743, -59) reference; L5 (59.743, -96)-(72.743, -78) reference; L6 (3.343, -113.359)-(3.343, -117.359); L7 (3.343, -117.359)-(5.343, -117.359); L8 (91.743, 0)-(93.743, 0); L9 (93.743, 0)-(89.731, -40.271); L10 (89.731, -40.271)-(88.73, -40.229); L11 (88.73, -40.229)-(83.574, -59.991); L12 (83.574, -59.991)-(82.596, -59.752); L13 (82.596, -59.752)-(74.952, -80.03); L14 (74.952, -80.03)-(74.214, -79.355); L15 (74.214, -79.355)-(61.106, -98.673); L16 (61.106, -98.673)-(25.92, -101.132); L17 (25.92, -101.132)-(8.876, -105.74); L18 (8.876, -105.74)-(5.343, -117.359); 1 further point
  constraints: 20 end point, 1 horizontal, 1 perpendicular, 1 vertical, 4 other
  dimensions: "d1605" = 4 distance of L6.start L6.end; "d1606" = 2 distance of L6.end L7.end; "d1607" = 2 distance of L1.start L8.end; "d1608" = 2 distance of L2.start L10.end; "d1609" = 3 distance of L2.start L9.end; "d1610" = 2 distance of L3.start L12.end; "d1611" = 3 distance of L3.start L11.end; "d1612" = 2 distance of L4.start L14.end; "d1613" = 3 distance of L4.start L13.end; "d1614" = 3 distance of L5.start L15.end
sketch "Skizze89"
  geometry: L1 (91.114, 0)-(75.114, 0) reference; L2 (85.614, -35)-(91.114, 0) reference; L3 (79.614, -53)-(85.614, -35) reference; L4 (70.614, -71)-(79.614, -53) reference; L5 (59.614, -89)-(70.614, -71) reference; L6 (4.975, -111.213)-(4.975, -114.213); L7 (4.975, -114.213)-(6.975, -114.213); L8 (91.114, 0)-(93.114, 0); L9 (93.114, 0)-(88.577, -35.469); L10 (88.577, -35.469)-(87.589, -35.312); L11 (87.589, -35.312)-(82.447, -53.985); L12 (82.447, -53.985)-(81.472, -53.739); L13 (81.472, -53.739)-(73.19, -72.537); L14 (73.19, -72.537)-(72.286, -72.096); L15 (72.286, -72.096)-(60.837, -91.739); L16 (60.837, -91.739)-(26.244, -97.38); L17 (26.244, -97.38)-(13.764, -101.005); L18 (13.764, -101.005)-(6.975, -114.213); 1 further point
  constraints: 20 end point, 1 horizontal, 1 perpendicular, 1 vertical, 4 other
  dimensions: "d1627" = 3 distance of L6.start L6.end; "d1628" = 2 distance of L6.end L7.end; "d1629" = 2 distance of L1.start L8.end; "d1630" = 2 distance of L2.start L10.end; "d1631" = 3 distance of L2.start L9.end; "d1632" = 2 distance of L3.start L12.end; "d1633" = 3 distance of L3.start L11.end; "d1634" = 2 distance of L4.start L14.end; "d1635" = 3 distance of L4.start L13.end; "d1636" = 3 distance of L5.start L15.end
sketch "Skizze90"
  geometry: L1 (85.969, 0)-(69.969, 0) reference; L2 (80.969, -29)-(85.969, 0) reference; L3 (75.969, -46)-(80.969, -29) reference; L4 (67.969, -63)-(75.969, -46) reference; L5 (57.469, -79.58)-(67.969, -63) reference; L6 (6.948, -102.881)-(6.948, -108.881); L7 (6.948, -108.881)-(8.948, -108.881); L8 (85.969, 0)-(87.969, 0); L9 (87.969, 0)-(84.093, -29.693); L10 (84.093, -29.693)-(83.117, -29.476); L11 (83.117, -29.476)-(79.037, -46.909); L12 (79.037, -46.909)-(77.886, -46.568); L13 (77.886, -46.568)-(70.605, -64.432); L14 (70.605, -64.432)-(69.726, -63.955); L15 (69.726, -63.955)-(59.113, -82.089); L16 (59.113, -82.089)-(38.286, -89.34); L17 (38.286, -89.34)-(13.441, -97.636); L18 (13.441, -97.636)-(8.948, -108.881); 1 further point
  constraints: 20 end point, 1 horizontal, 1 perpendicular, 1 vertical, 4 other
  dimensions: "d1651" = 6 distance of L6.start L6.end; "d1652" = 2 distance of L6.end L7.end; "d1653" = 2 distance of L1.start L8.end; "d1654" = 2.2 distance of L2.start L10.end; "d1655" = 3.2 distance of L2.start L9.end; "d1656" = 2 distance of L3.start L12.end; "d1657" = 3.2 distance of L3.start L11.end; "d1658" = 2 distance of L4.start L14.end; "d1659" = 3 distance of L4.start L13.end; "d1660" = 3 distance of L5.start L15.end
sketch "Skizze91"
  geometry: L1 (73.926, 0)-(57.926, 0) reference; L2 (71.131, -24)-(73.926, 0) reference; L3 (67.888, -40)-(71.131, -24) reference; L4 (59.888, -56)-(67.888, -40) reference; L5 (49.888, -70)-(59.888, -56) reference; L6 (10.332, -94.989)-(10.332, -99.989); L7 (10.332, -99.989)-(12.332, -99.989); L8 (73.926, 0)-(75.926, 0); L9 (75.926, 0)-(74.115, -24.309); L10 (74.115, -24.309)-(73.12, -24.206); L11 (73.12, -24.206)-(70.763, -40.855); L12 (70.763, -40.855)-(69.798, -40.593); L13 (69.798, -40.593)-(63.273, -58.131); L14 (63.273, -58.131)-(62.309, -57.772); L15 (62.309, -57.772)-(52.364, -73.141); A1 r 282.977 centre (189.391, -320.729) between (52.364, -73.141) and (12.332, -99.989); 1 further point
  constraints: 20 end point, 2 perpendicular, 2 point on circle, 1 centre point, 1 horizontal, 1 vertical, 1 other
  dimensions: "d1675" = 5 distance of L6.start L6.end; "d1676" = 2 distance of L6.end L7.end; "d1677" = 2 distance of L1.start L8.end; "d1678" = 2 distance of L2.start L10.end; "d1679" = 3 distance of L2.start L9.end; "d1680" = 2 distance of L3.start L12.end; "d1681" = 3 distance of L3.start L11.end; "d1682" = 3 distance of L4.start L14.end; "d1683" = 4 distance of L4.start L13.end; "d1684" = 4 distance of L5.start L15.end
feature "Verdickung11" dims "d1940" = 2, "d1941" = 2
feature "Verdickung12" dims "d1942" = 2, "d1943" = 2
feature "Verdickung13" dims "d1944" = 2, "d1945" = 2
feature "Verdickung14" dims "d1946" = 2, "d1947" = 2
feature "Verdickung15" dims "d1948" = 2, "d1949" = 2
feature "Verdickung16" dims "d1950" = 2, "d1951" = 2
feature "Verdickung17" dims "d1952" = 2, "d1953" = 2
sketch "Skizze94"
  geometry: L1 (-27.129, 91.87)-(-29, 126); L2 (-24.078, 74.319)-(-27.129, 91.87); L3 (-10.001, 59.923)-(-24.078, 74.319); L4 (8.284, 46.946)-(-10.001, 59.923); L5 (0, 75)-(-11, 77) reference; L6 (-19, 145)-(-35, 145) reference; L7 (-35, 145)-(-35, 79.993) reference; L8 (-29, 126)-(-31, 126); L9 (-30, 91)-(-29.043, 91.29); L10 (-29.043, 91.29)-(-27, 75); L11 (-27, 75)-(-25.903, 75.138); L12 (-25.903, 75.138)-(-13, 60); L13 (-13, 60)-(-11.986, 60.167); L14 (-11.986, 60.167)-(6, 45); L15 (14.029, 42.105)-(14.029, 40.105); L16 (-31, 126)-(-30.908, 106); L17 (-30.908, 106)-(-29.907, 106); L18 (-29.907, 106)-(-30, 91); A1 r 12 centre (-11, 89) between (-23, 89) and (-11, 77) reference; A2 r 24 centre (-11, 79.993) between (-35, 79.993) and (-23.36, 59.42) reference; A3 r 55.926 centre (-45.925, 10.152) between (10, 10) and (-21.487, 60.456) reference; A4 r 13.44 centre (3.46, 31.803) between (14.029, 40.105) and (6, 45); 4 further points; 2 other entities
  constraints: 30 end point, 2 horizontal, 2 point on circle, 1 centre point, 1 vertical, 5 other
  dimensions: "d2034" = 2 distance of L1.end L8.end; "d2035" = 2 distance of L1.start L9.end; "d2036" = 3 distance of L1.start L9.start; "d2037" = 2 distance of L2.start L11.end; "d2038" = 3 distance of L2.start L10.end; "d2039" = 2 distance of L3.start L13.end; "d2040" = 3 distance of L3.start L12.end; "d2041" = 3 distance of L4.start L14.end; "d2042" = 4 distance from line of L7 L8.end; "d2043" = 8 distance from line of L7 L10.end; "d2044" = 22 distance from line of L7 L12.end; "d2045" = 41 distance from line of L7 L14.end; "d2046" = 2 distance of L15.start L15.end; "d2058" = 19 distance between parallel lines of L6 L8; "d2060" = 16 vertical distance of L9.start L10.end; "d2061" = 15 vertical distance of L10.end L12.end; "d2062" = 15 vertical distance of L14.end L12.end; "d2064" = 5 distance from line of L7 L9.start; "d2065" = 2 distance from line of L1 L17.end; "d2066" = 3 distance from line of L1 L16.end; "d2067" = 20 distance between parallel lines of L8 L17; "d2142" = 15 vertical distance of L16.end L9.start
feature "Erhebung71" dims "d2191" = 0, "d2192" = 90 deg, "d2193" = 0, "d2194" = 90 deg, "d2195" = 0, "d2196" = 90 deg, "d2197" = 0, "d2198" = 90 deg, "d2199" = 0, "d2200" = 90 deg, "d2201" = 0, "d2202" = 90 deg, "d2203" = 0, "d2204" = 90 deg, "d2205" = 0, "d2206" = 90 deg, "d2207" = 0, "d2208" = 90 deg, "d2209" = 0, "d2210" = 90 deg, "d2211" = 0, "d2212" = 90 deg, "d2213" = 0, "d2214" = 90 deg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
feature "Erhebung73" dims "d2249" = 0, "d2250" = 90 deg, "d2251" = 0, "d2252" = 90 deg, "d2253" = 0, "d2254" = 90 deg, "d2255" = 0, "d2256" = 90 deg
feature "Erhebung74" dims "d2257" = 0, "d2258" = 90 deg, "d2259" = 0, "d2260" = 90 deg, "d2261" = 0, "d2262" = 90 deg
feature "Verdickung43" dims "d2268" = 9, "d2269" = 9
feature "Verdickung44" dims "d2270" = 8, "d2271" = 10
feature "Verdickung45" dims "d2272" = 4, "d2273" = 11
feature "Verdickung46" dims "d2274" = 2.5, "d2275" = 11
mirror "Spiegeln9"
workplane "Arbeitsebene23"
node "Volumenkörper1"
feature "Verdickung10" dims "d2266" = 9, "d2267" = 11
node "2024-08-05 Börteboot Kiel 001.ipt:1" dims "d0" = 10
node "2024-08-05 Börteboot Spanten 001.ipt:1" dims "d0" = 10
other parameters: "Stärke" = 0.5, "Biegeradius" = 0.5 (= Stärke), "BreiteBiegungsfreistellung" = 0.5 (= Stärke), "TiefeBiegungsfreistellung" = 0.25 (= 0.5 x Stärke), "GrößeEckenfreistellung" = 2 (= 4 x Stärke), "SeamGap" = 0.01, "MinimalRest" = 1 (= 2 x Stärke), "Übergangsradius" = 0.5 (= Biegeradius), "JacobiRadiusGröße" = 0.5 (= Biegeradius), "Abstandsgröße" = 0.5 (= Stärke), "d1539" = 90 deg, "d1548" = 90 deg, "d1558" = 90 deg, "d1570" = 90 deg, "d1581" = 90 deg, "d2276" = -4.5
